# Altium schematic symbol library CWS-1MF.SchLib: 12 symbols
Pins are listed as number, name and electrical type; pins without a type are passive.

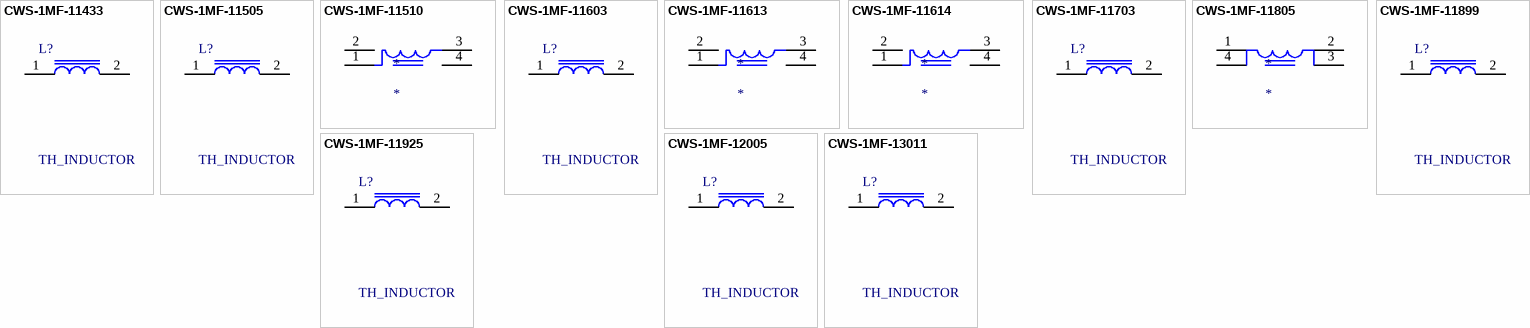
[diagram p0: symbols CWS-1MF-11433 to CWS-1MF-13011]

## CWS-1MF-11433
designator L?, comment TH_INDUCTOR
POWER INDUCTOR 35 A, 18 uH, 2 mOhms, OD 66.04 mm, HT 40.13 mm; Manufacturer #1: CWS; Current: 35 A; DCR: 2 mOhms; Inductance: 18 uH
footprint CWS-1MF-11433
pins: 1, 2

## CWS-1MF-11505
designator L?, comment TH_INDUCTOR
POWER INDUCTOR 4 A, 95 uH, 20 mOhms, OD 39.62 mm, HT 17.78 mm; Manufacturer #1: CWS; Current: 4 A; Inductance: 95 uH
footprint CWS-1MF-11505
pins: 1, 2

## CWS-1MF-11510
designator *
POWER INDUCTOR 4 A, 300 uH, 50 mOhms, OD 41.91 mm, HT 24.13 mm; Manufacturer #1: CWS; Current: 4 A; Inductance: 300 uH
footprint CWS-1MF-11510
pins: 1, 2, 3, 4

## CWS-1MF-11603
designator L?, comment TH_INDUCTOR
POWER INDUCTOR 16 A, 2.2 mH, 110 mOhms, OD 65.02 mm, HT 39.12 mm; Manufacturer #1: CWS; Current: 16 A; Inductance: 2.2 mH
footprint CWS-1MF-11603
pins: 1, 2

## CWS-1MF-11613
designator *
POWER INDUCTOR 7.2 A, 700 uH, 70 mOhms, OD 50.04 mm, HT 29.21 mm; Manufacturer #1: CWS; Current: 7.2 A; Inductance: 700 uH
footprint CWS-1MF-11613
pins: 1, 2, 3, 4

## CWS-1MF-11614
designator *
POWER INDUCTOR 9 A, 180 uH, 40 mOhms, OD 43.18 mm, HT 24.13 mm; Manufacturer #1: CWS; Current: 9 A; Inductance: 180 uH
footprint CWS-1MF-11614
pins: 1, 2, 3, 4

## CWS-1MF-11703
designator L?, comment TH_INDUCTOR
POWER INDUCTOR 16 A, 300 uH, 32 mOhms, OD 67.31 mm, HT 25.4 mm; Manufacturer #1: CWS; Current: 16 A; Inductance: 300 uH
footprint CWS-1MF-11703
pins: 1, 2

## CWS-1MF-11805
designator *
POWER INDUCTOR 25 A, 95 uH, 12 mOhms, OD 52.07 mm, HT 36.07 mm; Manufacturer #1: CWS; Current: 25 A; Inductance: 95 uH
footprint CWS-1MF-11805
pins: 1, 2, 3, 4

## CWS-1MF-11899
designator L?, comment TH_INDUCTOR
POWER INDUCTOR 8.5 A, 330 uH, 50 mOhms, OD 33.02 mm, HT 30.48 mm; Manufacturer #1: CWS; Current: 8.5 A; Inductance: 330 uH
footprint CWS-1MF-11899
pins: 1, 2

## CWS-1MF-11925
designator L?, comment TH_INDUCTOR
POWER INDUCTOR 25 A, 16 uH, 3 mOhms, OD 25.4 mm, HT 12.7 mm; Manufacturer #1: CWS; OD: 25.4 mm; Current: 25 A; DCR: 3 mOhms; Inductance: 16 uH
footprint CWS-1MF-11925
pins: 1, 2

## CWS-1MF-12005
designator L?, comment TH_INDUCTOR
POWER INDUCTOR 25 A, 12 uH, 7 mOhms, OD 41.91 mm, HT 17.02 mm; Manufacturer #1: CWS; Current: 25 A; DCR: 7 mOhms; Inductance: 12 uH
footprint CWS-1MF-12005
pins: 1, 2

## CWS-1MF-13011
designator L?, comment TH_INDUCTOR
POWER INDUCTOR 100 A, 170 uH, 9 mOhms, OD 89.92 mm, HT 70.1 mm; Manufacturer #1: CWS; Current: 100 A; DCR: 9 mOhms; Inductance: 170 uH
footprint CWS-1MF-13011
pins: 1, 2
